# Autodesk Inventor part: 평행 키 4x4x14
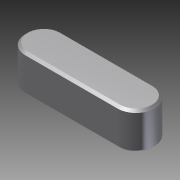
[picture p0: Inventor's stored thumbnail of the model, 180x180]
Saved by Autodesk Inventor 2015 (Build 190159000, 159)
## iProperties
Created: 2024-12
Part Number: 평행 키 4x4x14
Material: 일반
Document SubType Name: Modeling
Designer: 102566
Density: 1 g/cm^3
Appearance: 기본값
Author: 102566
Author: jhkim
Description: 키 및 해당 키홈
Creation Date: 2024-12-12
Sending System: Autodesk Inventor 2025
Preprocessor: ST-DEVELOPER v20
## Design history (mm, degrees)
node "평행 키 4x4x141"
body "Solid1"
node "기준1"
